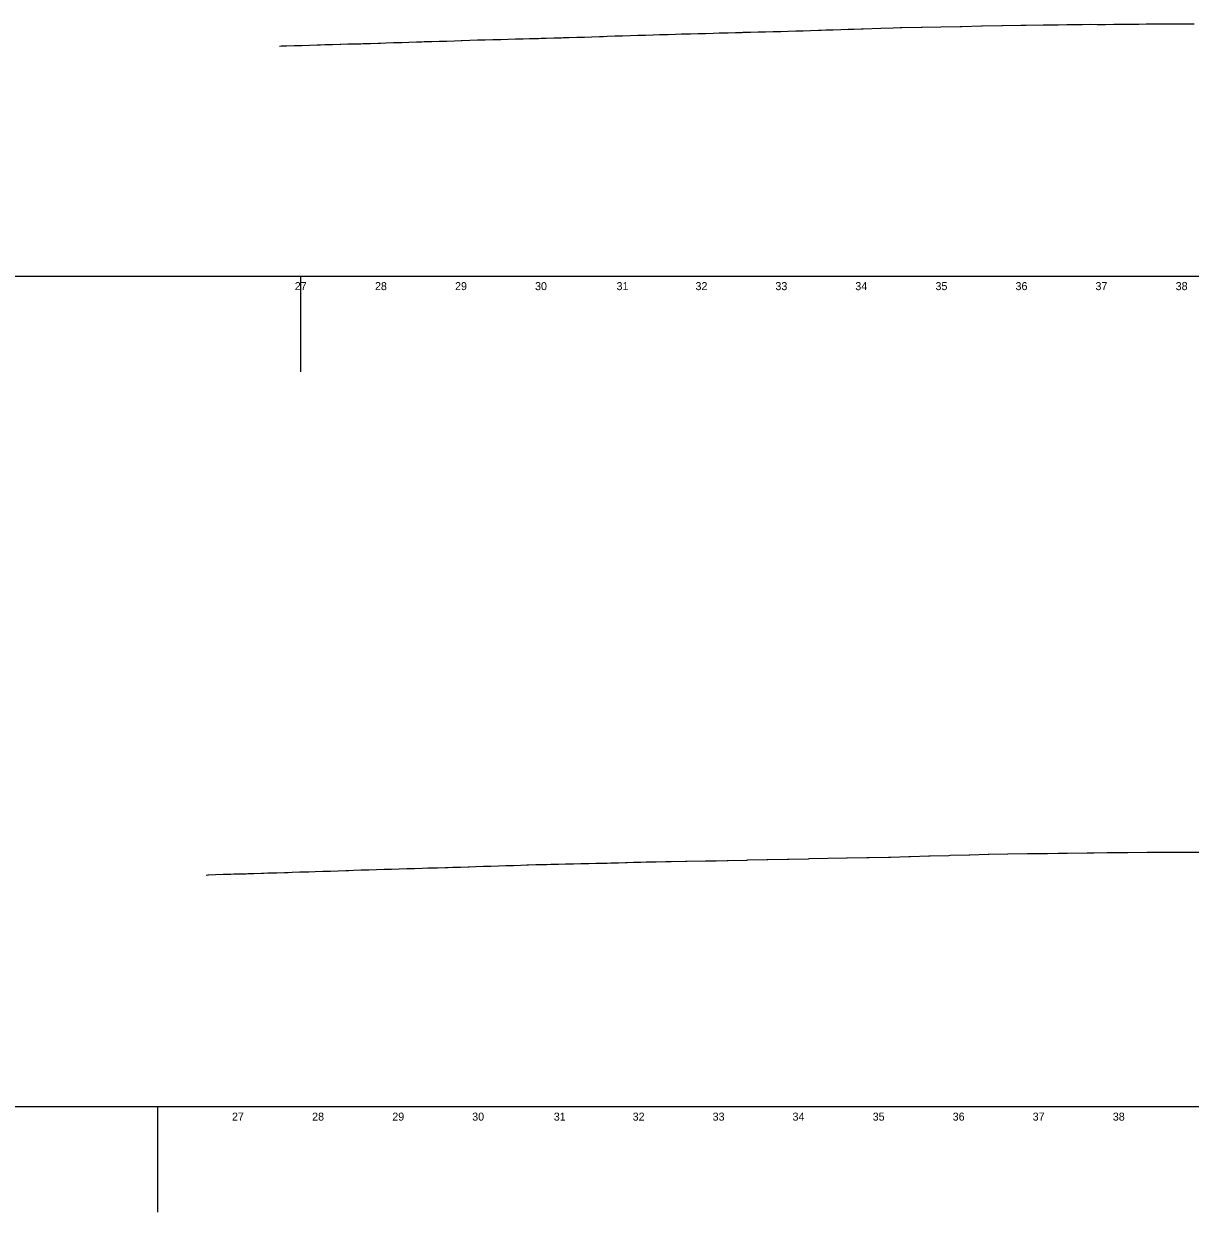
# Model space of a CAD drawing. Extents: x 579185 to 595036, y -53221 to -44640.
# Drawn here: x 580642 to 582099, y -46169 to -44685 of the extents above; entities that cross this region are included whole.
import ezdxf

# ---------------------------------------------------------------- set-up
doc = ezdxf.new("R2010")
doc.units = 0
for name, color, linetype in [('Default', 7, 'Continuous'), ('Exist Profile Cell', 7, 'Continuous'), ('Exist Vertical Profile Ground Line', 7, 'Continuous'), ('Exist Vertical Profile Horizontal Axis Label Major', 7, 'Continuous')]:
    doc.layers.add(name, color=color, linetype=linetype)

msp = doc.modelspace()

# ---------------------------------------------------------------- linework, layer by layer
at = {"layer": 'Default'}
for p, q in [((580987.9, -45119.4), (580987.9, -45000)), ((580809.4, -46169.4), (580809.4, -46037.5))]:
    msp.add_line(p, q, dxfattribs=at)
at = {"layer": 'Exist Profile Cell'}
for p, q in [((579221, -45000), (594884.8, -45000)), ((579243, -46037.5), (595036.4, -46037.5))]:
    msp.add_line(p, q, dxfattribs=at)
at = {"layer": 'Exist Vertical Profile Ground Line'}
for points in [[(581512.2, -44696.1), (581521.4, -44695.9), (581530.8, -44695.7), (581535.6, -44695.5), (581537.2, -44695.5), (581538.8, -44695.5), (581540.2, -44695.4), (581549.5, -44695.2), (581558.9, -44695), (581562.2, -44694.9), (581563.3, -44694.9), (581568.3, -44694.8), (581577.7, -44694.5), (581587.1, -44694.3), (581596.4, -44694), (581605.8, -44693.7), (581610.9, -44693.6), (581612.4, -44693.6), (581615.2, -44693.5), (581624.5, -44693.2), (581633.9, -44692.8), (581637, -44692.7), (581637.6, -44692.7), (581643.3, -44692.5), (581650.3, -44692.3), (581652.7, -44692.2), (581662.3, -44691.9), (581671.4, -44691.6), (581679, -44691.4), (581687.4, -44691.1), (581690.2, -44691), (581712.2, -44690.4), (581727.7, -44689.9), (581736.4, -44689.6), (581737.4, -44689.6), (581738.4, -44689.6), (581762.5, -44688.9), (581763.8, -44688.9), (581787.3, -44688.5), (581811.1, -44688.1), (581812.2, -44688), (581813.2, -44688), (581837.8, -44687.5), (581838.8, -44687.5), (581863.4, -44687), (581864.3, -44687), (581886.8, -44686.6), (581893.7, -44686.5), (581914.8, -44686.2), (581923.5, -44686.1), (581933.7, -44685.9), (581944.4, -44685.7), (581953.7, -44685.7), (581963.5, -44685.6), (581973.4, -44685.4), (581982.4, -44685.5), (581983, -44685.5), (581992.9, -44685.5), (582003, -44685.3), (582013, -44685.2), (582023.1, -44685.1), (582034.4, -44685.1), (582043.5, -44684.9), (582053, -44685), (582063.1, -44684.9), (582072.7, -44684.9), (582078.4, -44684.8), (582083.4, -44684.8), (582090, -44684.8), (582093.3, -44684.7), (582103.3, -44684.7)], [(580961.2, -44712.8), (580963.4, -44712.5), (580965.1, -44712.5), (580970.1, -44712.3), (580979.6, -44712), (580988, -44711.8), (580989.1, -44711.7), (580998.7, -44711.4), (581008.2, -44711.1), (581012.5, -44711), (581017.7, -44710.8), (581027.3, -44710.6), (581036.8, -44710.3), (581037.6, -44710.3), (581046.3, -44710), (581055.9, -44709.7), (581061.3, -44709.6), (581062.6, -44709.6), (581065.4, -44709.5), (581074.9, -44709.2), (581084.5, -44708.9), (581086.2, -44708.8), (581087.5, -44708.8), (581094, -44708.6), (581103.5, -44708.3), (581111, -44708.1), (581112.3, -44708), (581113.1, -44708), (581113.8, -44708), (581122.6, -44707.7), (581132.1, -44707.4), (581137.9, -44707.3), (581139.1, -44707.2), (581141.7, -44707.1), (581151.2, -44706.9), (581160.7, -44706.6), (581163.4, -44706.5), (581164.5, -44706.5), (581170.3, -44706.3), (581179.8, -44706), (581188, -44705.7), (581188.5, -44705.7), (581189.3, -44705.7), (581198.9, -44705.3), (581208.4, -44705), (581212, -44704.9), (581212.6, -44704.9), (581213.3, -44704.9), (581217.9, -44704.7), (581227.5, -44704.5), (581237.5, -44704.2), (581246.7, -44704), (581256.1, -44703.7), (581261.7, -44703.6), (581262.2, -44703.6), (581262.6, -44703.6), (581265.6, -44703.5), (581273.5, -44703.3), (581275.1, -44703.2), (581284.7, -44703), (581287.9, -44702.9), (581288.6, -44702.9), (581294.2, -44702.7), (581303.7, -44702.4), (581313.5, -44702.2), (581315.5, -44702.1), (581322.8, -44701.9), (581332.3, -44701.6), (581338.5, -44701.4), (581340.5, -44701.3), (581341.9, -44701.3), (581351.4, -44701), (581360.9, -44700.7), (581363.5, -44700.6), (581365.6, -44700.5), (581370.5, -44700.4), (581380, -44700), (581387.9, -44699.8), (581389.5, -44699.7), (581399.1, -44699.4), (581408.6, -44699.1), (581410.2, -44699.1), (581412.3, -44699), (581418.1, -44698.8), (581427.7, -44698.6), (581435.8, -44698.3), (581437, -44698.3), (581437.8, -44698.3), (581439.9, -44698.2), (581446.4, -44698), (581455.8, -44697.8), (581463.4, -44697.5), (581465.2, -44697.5), (581465.5, -44697.5), (581474.5, -44697.2), (581483.9, -44696.9), (581487.8, -44696.8), (581493.3, -44696.7), (581502.7, -44696.4), (581510.1, -44696.2), (581512.2, -44696.1)], [(581422, -45731.9), (581431.4, -45731.7), (581443.6, -45731.5), (581445.2, -45731.4), (581450.1, -45731.3), (581468.2, -45731), (581468.9, -45731), (581470, -45731), (581493.1, -45730.6), (581495.1, -45730.6), (581497, -45730.5), (581506.4, -45730.4), (581520.1, -45730.1), (581521.5, -45730.1), (581544.6, -45729.5), (581545.9, -45729.4), (581569.6, -45728.8), (581571, -45728.8), (581595.8, -45728.3), (581597.1, -45728.3), (581622, -45727.8), (581623.1, -45727.7), (581646.1, -45727.3), (581669.3, -45726.8), (581670.1, -45726.7), (581694.7, -45726.3), (581696.1, -45726.3), (581697.5, -45726.3), (581721.9, -45725.9), (581724.2, -45725.8), (581747, -45725.1), (581749.1, -45725.1), (581772.1, -45724.3), (581773.8, -45724.2), (581797.2, -45723.6), (581798.7, -45723.5), (581822.4, -45722.9), (581823.5, -45722.8), (581846.3, -45722.3), (581847.2, -45722.3), (581870.2, -45721.8), (581870.9, -45721.8), (581895.2, -45721.5), (581895.6, -45721.5), (581920.3, -45721.1), (581933.5, -45720.9), (581945.1, -45720.8), (581970, -45720.4), (581978.1, -45720.3), (581994.9, -45720.2), (581995.3, -45720.2), (582019.9, -45720), (582020.8, -45720), (582044.9, -45719.8), (582046, -45719.8), (582069.9, -45719.6), (582071.1, -45719.6), (582095.1, -45719.6), (582095.9, -45719.6), (582120.2, -45719.6)], [(580869.4, -45748.5), (580871.8, -45748), (580872.4, -45747.9), (580881.4, -45747.6), (580890.9, -45747.3), (580897, -45747.1), (580900.5, -45747), (580904, -45746.9), (580910, -45746.7), (580919.6, -45746.5), (580921.8, -45746.4), (580929.2, -45746.2), (580938.7, -45745.9), (580941, -45745.8), (580946.7, -45745.6), (580948.3, -45745.6), (580957.8, -45745.3), (580967.4, -45745), (580971.6, -45744.9), (580972.1, -45744.9), (580976.9, -45744.7), (580986.5, -45744.4), (580996.1, -45744.1), (580997, -45744.1), (580997.6, -45744.1), (581005.6, -45743.8), (581015.2, -45743.5), (581022.3, -45743.3), (581022.9, -45743.3), (581024.7, -45743.2), (581034.3, -45742.9), (581043.9, -45742.5), (581047.2, -45742.4), (581047.8, -45742.4), (581053.4, -45742.2), (581063, -45741.9), (581072.1, -45741.6), (581072.8, -45741.6), (581082.1, -45741.3), (581091.7, -45741), (581097, -45740.9), (581098, -45740.8), (581101.2, -45740.7), (581110.8, -45740.5), (581120.3, -45740.2), (581121.8, -45740.1), (581123.2, -45740.1), (581129.9, -45739.9), (581139.5, -45739.6), (581146.6, -45739.4), (581147.5, -45739.4), (581149, -45739.4), (581158.6, -45739.1), (581168.1, -45738.8), (581171.5, -45738.7), (581171.9, -45738.7), (581177.7, -45738.5), (581187.3, -45738.2), (581196.8, -45737.9), (581198, -45737.9), (581206.4, -45737.6), (581215.8, -45737.3), (581222.1, -45737.1), (581224, -45737), (581225.1, -45737), (581234.5, -45736.7), (581243.9, -45736.4), (581246.1, -45736.3), (581247.9, -45736.3), (581253.3, -45736.1), (581262.6, -45735.8), (581270, -45735.6), (581272, -45735.5), (581281.4, -45735.2), (581290.8, -45735), (581293.2, -45734.9), (581295.1, -45734.9), (581300.1, -45734.8), (581309.5, -45734.6), (581318.2, -45734.4), (581318.9, -45734.4), (581320.1, -45734.3), (581328.3, -45734.1), (581337.6, -45733.9), (581343, -45733.8), (581345.1, -45733.7), (581347, -45733.7), (581347.4, -45733.7), (581356.4, -45733.5), (581365.8, -45733.3), (581370.2, -45733.2), (581375.1, -45733), (581384.5, -45732.8), (581393.3, -45732.6), (581393.9, -45732.6), (581395.3, -45732.5), (581403.3, -45732.3), (581412.6, -45732.1), (581419, -45731.9), (581420.3, -45731.9), (581422, -45731.9)]]:
    msp.add_lwpolyline(points, dxfattribs=at)

# ---------------------------------------------------------------- texts
at = {"layer": 'Exist Vertical Profile Horizontal Axis Label Major'}
for s, p in [('27', (580980.2, -45017.5)), ('28', (581080.4, -45017.5)), ('29', (581180.4, -45017.5)), ('30', (581280.3, -45017.5)), ('31', (581382.1, -45017.5)), ('32', (581480.7, -45017.5)), ('33', (581580.5, -45017.5)), ('34', (581680.3, -45017.5)), ('35', (581780.4, -45017.5)), ('36', (581880.4, -45017.5)), ('37', (581980.2, -45017.5)), ('38', (582080.4, -45017.5)), ('27', (580901.8, -46055)), ('28', (581001.9, -46055)), ('29', (581102, -46055)), ('30', (581201.8, -46055)), ('31', (581303.7, -46055)), ('32', (581402.2, -46055)), ('33', (581502.1, -46055)), ('34', (581601.9, -46055)), ('35', (581702, -46055)), ('36', (581801.9, -46055)), ('37', (581901.8, -46055)), ('38', (582001.9, -46055))]:
    msp.add_text(s, height=10, dxfattribs=at).set_placement(p)

doc.saveas('drawing.dxf')
